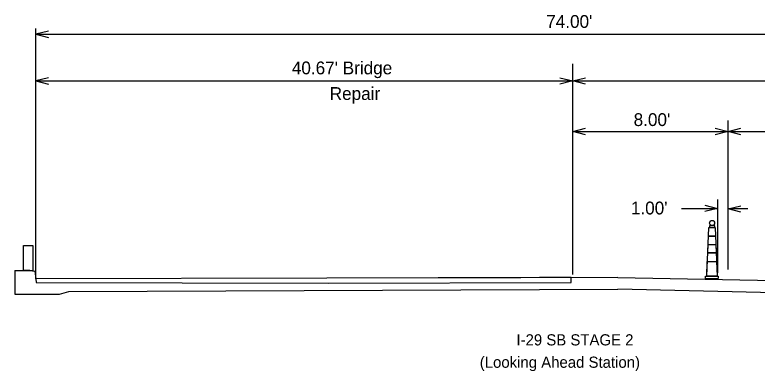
# Model space of a CAD drawing. Extents: x 8771 to 81668, y 6145 to 11018.
# Drawn here: x 14284 to 15600, y 6758 to 7389 of the extents above; entities that cross this region are included whole.
import ezdxf

# ---------------------------------------------------------------- set-up
doc = ezdxf.new("R2010")
doc.units = 0
for name, color, linetype in [('dsnCellElements', 7, 'Continuous'), ('DsnShtRevisedText', 7, 'Continuous'), ('Level 8', 7, 'Continuous'), ('ShtPlotIdentification', 7, 'Continuous')]:
    doc.layers.add(name, color=color, linetype=linetype)

msp = doc.modelspace()

# ---------------------------------------------------------------- linework, layer by layer
at = {"layer": 'dsnCellElements'}
for p, q in [((14320.7, 6921), (14320.7, 7364.6)), ((14320.7, 7354.6), (16224.9, 7354.6)), ((15272.8, 6929), (15272.8, 7302)), ((14320.7, 7271.9), (15272.8, 7271.9)), ((14479.4, 7271.9), (15272.8, 7271.9)), ((15272.8, 7271.9), (16224.9, 7271.9)), ((15548.3, 6937.8), (15548.3, 7201.9)), ((15272.8, 7182.4), (15858.5, 7182.4)), ((15529.8, 6932.2), (15529.8, 7061.6)), ((15465.7, 7046), (15529.7, 7046)), ((15583, 7045.2), (15548.3, 7045.2)), ((14310.2, 6935.8), (14298.8, 6935.8)), ((14315.4, 6935.3), (14310.2, 6935.8)), ((14363.2, 6894.2), (14379.4, 6898.6)), ((14379.4, 6898.6), (15352.9, 6902.8)), ((16166.2, 6884.8), (15352.9, 6902.8))]:
    msp.add_line(p, q, dxfattribs=at)
for points in [[(14343.4, 7360.3), (14320.7, 7354.6), (14343.4, 7348.9)], [(14343.4, 7277.5), (14320.7, 7271.9), (14343.4, 7266.2)], [(15250.1, 7277.5), (15272.8, 7271.9), (15250.1, 7266.2)], [(15295.5, 7266.2), (15272.8, 7271.9), (15295.5, 7277.5)], [(15295.5, 7176.7), (15272.8, 7182.4), (15295.5, 7188.1)], [(15525.6, 7188.1), (15548.3, 7182.4), (15525.6, 7176.7)], [(15571, 7176.7), (15548.3, 7182.4), (15571, 7188.1)], [(15507, 7051.6), (15529.7, 7046), (15507, 7040.3)], [(15571, 7039.5), (15548.3, 7045.2), (15571, 7050.9)], [(14298.8, 6935.8), (14298.8, 6980.3), (14315.4, 6980.3), (14315.4, 6935.3)], [(14283.7, 6935.8), (14283.7, 6894.2), (14363.2, 6894.2)], [(14283.7, 6935.8), (14310.2, 6935.8), (14319.2, 6934.9), (14320.7, 6921)]]:
    msp.add_lwpolyline(points, dxfattribs=at)
at = {"layer": 'DsnShtRevisedText'}
msp.add_lwpolyline([(14298.8, 6935.8), (14298.8, 6980.3), (14315.4, 6980.3), (14315.4, 6935.3)], dxfattribs=at)
at = {"layer": 'Level 8'}
for p, q in [((15510.3, 6925.8), (15514.1, 7012.1)), ((15513.4, 6997.1), (15514.1, 7012.1)), ((15514.1, 7012.1), (15525.3, 7012.1)), ((15514.1, 7012.1), (15525.3, 7012.1)), ((15525.3, 7012.1), (15529.1, 6925.8)), ((15525.3, 7012.1), (15526, 6997.1)), ((15513.4, 6997.1), (15526, 6997.1)), ((15526, 6997.1), (15513.4, 6997.1)), ((15512.1, 6967.1), (15512.8, 6982.1)), ((15512.8, 6982.1), (15526.6, 6982.1)), ((15512.8, 6982.1), (15526.6, 6982.1)), ((15526.6, 6982.1), (15527.3, 6967.1)), ((15512.1, 6967.1), (15527.3, 6967.1)), ((15527.3, 6967.1), (15512.1, 6967.1)), ((15510.3, 6925.8), (15511.4, 6952.1)), ((15511.4, 6952.1), (15527.9, 6952.1)), ((15511.4, 6952.1), (15527.9, 6952.1)), ((15527.9, 6952.1), (15529.1, 6925.8)), ((15508.4, 6925.8), (15530.9, 6925.8)), ((15508.4, 6922.1), (15508.4, 6925.8)), ((15529.1, 6925.8), (15510.3, 6925.8)), ((15530.9, 6925.8), (15530.9, 6922.1)), ((15508.4, 6922.1), (15530.9, 6922.1))]:
    msp.add_line(p, q, dxfattribs=at)
msp.add_lwpolyline([(15524.6, 7015.1), (15515, 7015.1), (15515, 7012.1), (15524.6, 7012.1)], close=True, dxfattribs=at)
msp.add_circle((15519.8, 7020.2), 4.5, dxfattribs=at)
at = {"layer": 'ShtPlotIdentification'}
for p, q in [((15352.9, 6923.7), (14320.7, 6921)), ((15352.9, 6923.7), (16224.9, 6907.2)), ((14839, 6913.8), (15270, 6915)), ((15270, 6915), (15270.1, 6919.5))]:
    msp.add_line(p, q, dxfattribs=at)
for points in [[(14836.8, 6922.4), (14320.7, 6921), (14321.3, 6914.7), (14839, 6913.8)], [(15270.1, 6919.5), (15270.1, 6923.5), (15258.1, 6923.5), (15239.6, 6923.4), (15213.6, 6923.4), (15180.8, 6923.3), (15133.7, 6923.1), (15068.4, 6923), (15034, 6922.9), (14836.8, 6922.4)]]:
    msp.add_lwpolyline(points, dxfattribs=at)

# ---------------------------------------------------------------- texts
at = {"layer": 'dsnCellElements'}
for s, height, p in [("74.00'", 22.71, (15225.8, 7365.9)), ("40.67' Bridge", 22.709, (14774.8, 7283.6)), ('Repair', 22.71, (14842, 7238.2)), ("8.00'", 22.71, (15380.8, 7192)), ("1.00'", 22.71, (15375.9, 7035.4)), ('I-29 SB STAGE 2', 19.8, (15173, 6803.3)), ('(Looking Ahead Station)', 19.8, (15108, 6763.7))]:
    msp.add_text(s, height=height, dxfattribs=at).set_placement(p)

doc.saveas('drawing.dxf')
